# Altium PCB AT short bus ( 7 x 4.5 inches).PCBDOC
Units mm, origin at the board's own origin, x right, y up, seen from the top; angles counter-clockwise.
Board outline 100 x 65 mm, 2 copper layers (TopLayer, BottomLayer); 8 components, 31 nets, 75 pads, 17 vias.
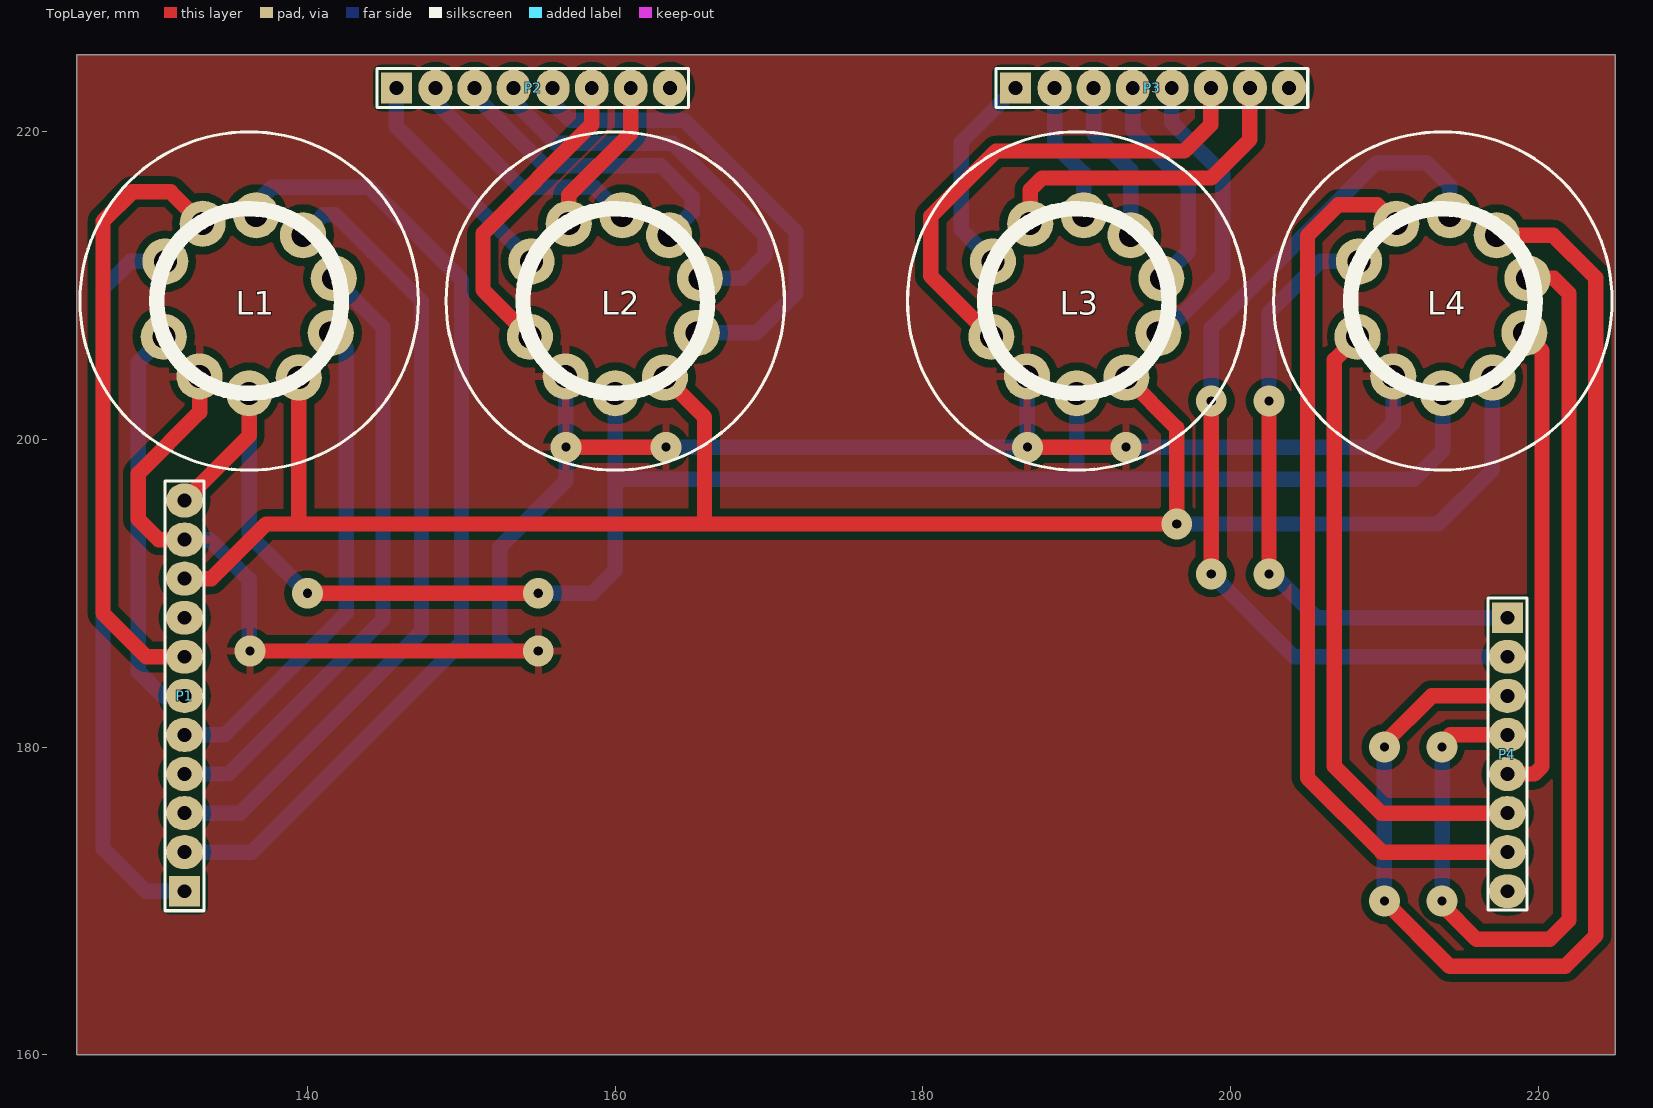
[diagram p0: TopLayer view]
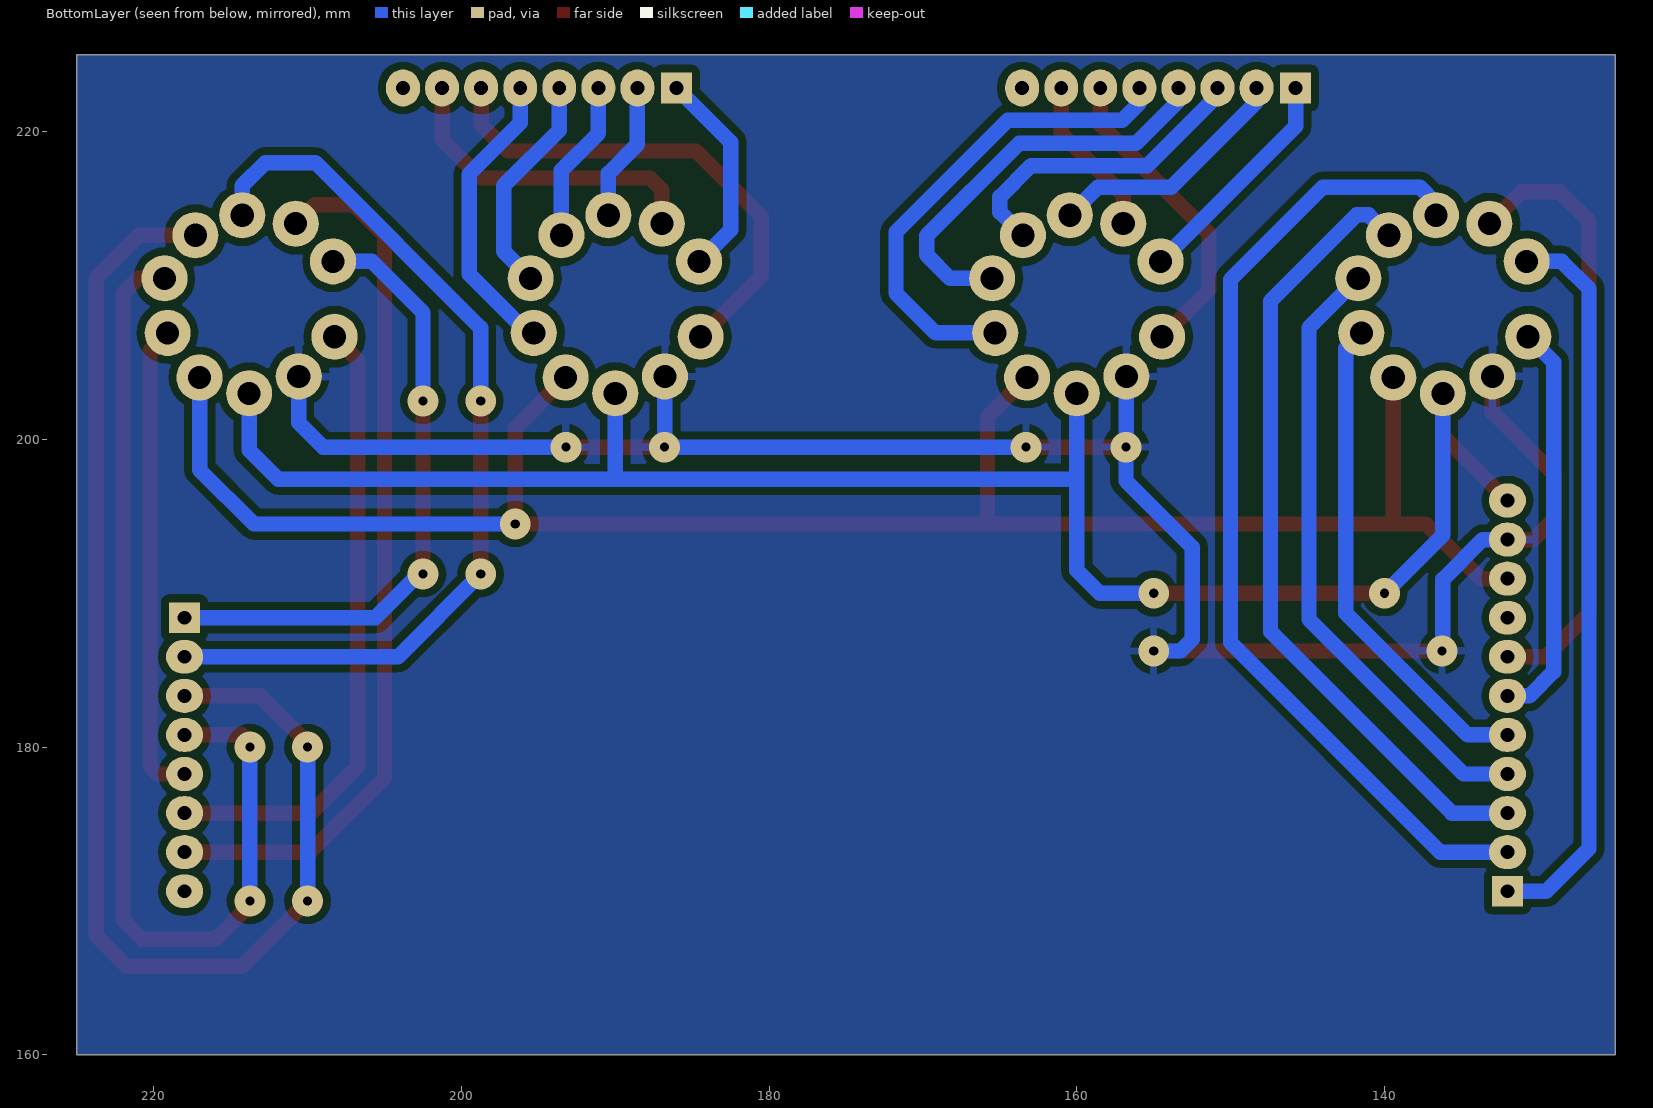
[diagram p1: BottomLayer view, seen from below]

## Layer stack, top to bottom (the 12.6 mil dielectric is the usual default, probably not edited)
TopSolder: solder mask 0.0102, Solder Resist, Dk 3.5
TopLayer: signal copper 0.0356
Dielectric1: core 0.32, FR-4, Dk 4.8
BottomLayer: signal copper 0.0356
BottomSolder: solder mask 0.0102, Solder Resist, Dk 3.5

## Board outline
125,225 225,225 225,160 125,160

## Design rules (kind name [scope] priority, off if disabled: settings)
Clearance [All] p1: gap=0.5 ignorepadtopadclearanceinfootprint=FALSE except(0: Arc-Hole Track-Hole SMDPad-Hole THPad-Hole Via-Hole Fill-Hole Poly-Hole Region-Hole Text-Hole)
FabricationTestPointUsage TestPointUsage [All] p1: valid=0 allowmultiple=FALSE
FabricationTestpoint Testpoint [All] p1: side=3 testpointundercomponent=TRUE minsize=1.016 maxsize=2.54 preferedsize=1.524 minholesize=0.508 maxholesize=1.016 preferedholesize=0.813 testpointgrid=0.025 allowsidetop=TRUE allowsidebottom=TRUE usegrid=TRUE gridtolerance=0
PasteMaskExpansion PasteMaskExpansion_1 [InComponent('P1')] p1: expansion=-3.81
PasteMaskExpansion [All] p2: expansion=0
PlaneClearance [All] p1: clearance=0.254
PolygonConnect [All] p1: connectstyle=Relief reliefconductorwidth=0.5 reliefentries=4 polygonreliefangle="90 Angle" airgapwidth=0.5
RoutingVias [All] p1: holewidth=0.711 width=1.27 viastyle="Through Hole" minholewidth=0.711 minwidth=1.27 maxholewidth=0.711 maxwidth=1.27
SilkToSolderMaskClearance SilkscreenOverComponentPads [IsPad] p1: minsilkscreentomaskgap=0.254 clearancetoexposedcopper=TRUE
SolderMaskExpansion [All] p1: expansion=0.051
Width [All] p1: maxlimit=2 minlimit=0.254 preferedwidth=1
25 further rules are at their usual default settings.

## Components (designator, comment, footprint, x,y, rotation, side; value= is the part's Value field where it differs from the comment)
L1 "IV-12" IV-12 136.2,209 r0 top
L2 "IV-12" IV-12 160,209 r0 top
L3 "IV-12" IV-12 190,209 r0 top
L4 "IV-12" IV-12 213.8,209 r0 top
P1 "Header 11" HDR1X11 132,170.63 r90 top
P2 "Header 8" HDR1X8 145.77,222.85 r0 top
P3 "Header 8" HDR1X8 186.02,222.85 r0 top
P4 "Header 8" HDR1X8 218,188.41 r270 top

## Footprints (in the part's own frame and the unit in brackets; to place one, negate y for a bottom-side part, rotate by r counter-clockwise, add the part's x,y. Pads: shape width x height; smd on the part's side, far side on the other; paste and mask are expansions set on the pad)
HDR1X8 [mm] "Connector; Header; 11 Position"
  rect 2x2 hole 0.9: 1(0,0)
  oval 2.2x2.4 hole 0.9: 2(2.54,0) 3(5.08,0) 4(7.62,0) 5(10.16,0) 6(12.7,0) 7(15.24,0) 8(17.78,0)
  silkscreen extent -1.27,-1.27 19,1.27
HDR1X11 [mm] "Connector; Header; 11 Position"
  rect 2x2 hole 0.9: 1(0,0)
  oval 2.2x2.4 hole 0.9: 2(2.54,0) 3(5.08,0) 4(7.62,0) 5(10.16,0) 6(12.7,0) 7(15.24,0) 8(17.78,0) 9(20.32,0) 10(22.86,0) 11(25.4,0)
  silkscreen extent -1.27,-1.27 26.67,1.27
IV-12 [mm]
  round 3 hole 1.5: 1(-5.55,-2.325) 2(-3.225,-4.9) 3(0,-6) 4(3.225,-4.975) 5(5.3,-2.075) 6(5.5,1.475) 7(3.5,4.275) 8(0.45,5.575) 9(-3.025,5.025) 10(-5.45,2.575)
  silkscreen extent -11,-11 11,11

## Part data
L1 L2 L3 L4: library part Lamp1_IV-12
P1: "Header, 11-Pin"
P2 P3 P4: "Header, 8-Pin"

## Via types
v1: diameter 2, hole 0.6, TopLayer to BottomLayer, 17 vias

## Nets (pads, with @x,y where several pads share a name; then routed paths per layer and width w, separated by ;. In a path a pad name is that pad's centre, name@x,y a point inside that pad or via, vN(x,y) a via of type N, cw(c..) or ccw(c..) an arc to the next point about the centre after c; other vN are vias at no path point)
Glow1: L1.3 L2.3 L3.3 L4.3 P1.11 | length 119.4
  TopLayer w1: P1.11 136.2,200.23 L1.3 ; v1(140,190) v1(155,190)
  BottomLayer w1: L1.3 136.2,193.8 v1(140,190) ; v1(155,190) 158.5,190 160,191.5 160,197.4 ; L2.3 160,197.4 ; L3.3 190,197.6 189.8,197.4 ; L4.3 213.8,199.3 211.9,197.4 189.8,197.4 ; 160,197.4 189.8,197.4
Glow2: L1.2 L2.2 L3.2 L4.2 P1.10 | length 126.7
  TopLayer w1: P1.10 130.31,193.49 129,194.8 129,197.8 132.975,201.775 L1.2 ; v1(136.25,186.25) v1(155,186.25) ; v1@156.7,199.5 v1(156.8,199.5) v1(163.3,199.5) ; v1(186.8,199.5) v1@193,199.5
  BottomLayer w1: P1.10 133.61,193.49 136.2,190.9 v1@136.2,186.5 ; v1(155,186.25) 153.25,186.25 152.5,187 152.5,193 156.8,197.3 v1(156.8,199.5) 156.775,199.525 L2.2 ; v1@163.1,199.5 v1(163.3,199.5) v1@186.775,199.5 ; v1@186.775,199.775 L3.2 ; v1@193,199.5 v1(193.2,199.5) 209,199.5 210.575,201.075 L4.2
Grid: L1.4 L2.4 L3.4 L4.4 P1.9 | length 124.5
  TopLayer w1: P1.9 133.75,190.95 137.3,194.5 v1(196.5,194.5) 196.5,200.75 L3.4 ; 139.425,194.75 L1.4 ; L2.4 165.8,201.45 165.8,194.75
  BottomLayer w1: v1(196.5,194.5) 213.5,194.5 217.025,198.025 L4.4
L1_a: L1.10 P1.1 | length 47.6
  BottomLayer w1: L1.10 128.475,211.575 126.7,209.8 126.7,173.4 129.47,170.63 P1.1
L1_b: L1.8 P1.2 | length 64.3
  BottomLayer w1: P1.2 136.37,173.17 150,186.8 150,210.4 144,216.4 137.7,216.4 136.65,215.35 L1.8
L1_c: L1.7 P1.3 | length 52.4
  BottomLayer w1: P1.3 135.61,175.71 147.4,187.5 147.4,209 141.8,214.6 141.025,214.6 L1.7
L1_d: L1.6 P1.4 | length 40.6
  BottomLayer w1: P1.4 134.85,178.25 144.9,188.3 144.9,207.275 L1.6
L1_e: L1.5 P1.5 | length 32.4
  BottomLayer w1: P1.5 134.59,180.79 142.5,188.7 142.5,205.925 L1.5
L1_f: L1.1 P1.6 | length 26.1
  BottomLayer w1: L1.1 129,205.025 129,184.9 130.57,183.33 P1.6
L1_g: L1.9 P1.7 | length 40.1
  TopLayer w1: P1.7 129.53,185.87 126.7,188.7 126.7,214.2 128.6,216.1 131.1,216.1 L1.9
L2_a: L2.10 P2.1 | length 14.9
  BottomLayer w1: P2.1 145.77,220.355 L2.10
L2_b: L2.8 P2.2 | length 16.1
  BottomLayer w1: P2.2 148.31,221.94 153.85,216.4 158.625,216.4 L2.8
L2_c: L2.7 P2.3 | length 19.9
  BottomLayer w1: P2.3@150.9,222.3 155.4,217.8 162.975,217.8 165,215.775 165,214.775 L2.7
L2_d: L2.6 P2.4 | length 27
  BottomLayer w1: P2.4 153.39,222.01 156.15,219.25 163.75,219.25 169.75,213.25 169.75,212 168.225,210.475 L2.6
L2_e: L2.5 P2.5 | length 31.8
  BottomLayer w1: P2.5 155.93,221.87 157.05,220.75 164.5,220.75 171.75,213.5 171.75,209.5 169.175,206.925 L2.5
L2_f: L2.1 P2.6 | length 20.4
  TopLayer w1: L2.1 151.4,209.725 151.4,213.4 158.47,220.47 P2.6
L2_g: L2.9 P2.7 | length 10.5
  TopLayer w1: L2.9 156.975,215.875 161.01,219.91 P2.7
L4_a: L3.10 P3.1 | length 13.6
  BottomLayer w1: L3.10 182.5,213.625 182.5,219.33 P3.1
L4_b: L3.8 P3.2 | length 9.1
  BottomLayer w1: P3.2 188.56,219.19 190.45,217.3 L3.8
L4_c: L3.7 P3.3 | length 10.6
  BottomLayer w1: P3.3 191.1,219.9 193.5,217.5 L3.7
L4_d: L3.6 P3.4 | length 14.6
  BottomLayer w1: P3.4 193.64,220.11 197.25,216.5 197.25,212.225 L3.6
L4_e: L3.5 P3.5 | length 19.3
  BottomLayer w1: L3.5 195.675,206.925 199.5,210.75 199.5,217.25 196.18,220.57 P3.5
L4_f: L3.1 P3.6 | length 32.5
  TopLayer w1: L3.1 180.5,210.625 180.5,214.5 184.75,218.75 197,218.75 198.72,220.47 P3.6
L4_g: L3.9 P3.7 | length 21.2
  TopLayer w1: L3.9 186.975,216.225 187.75,217 198.75,217 201.26,219.51 P3.7
L5_a: L4.10 P4.1 | length 39.9
  TopLayer w1: v1(202.5,191.25) v1(202.5,202.5)
  BottomLayer w1: v1@202.5,203.25 202.5,208.25 205.825,211.575 L4.10 ; v1@202.75,191.25 205.59,188.41 P4.1
L5_b: L4.8 P4.2 | length 60
  TopLayer w1: v1(198.75,191.25) v1(198.75,202.5)
  BottomLayer w1: v1(198.75,191.25) 204.13,185.87 P4.2 ; v1(198.75,202.5) 198.75,207.25 209.5,218 212.75,218 214.25,216.5 L4.8
L5_c: L4.7 P4.3 | length 86.1
  TopLayer w1: v1@209.875,180.125 213.08,183.33 P4.3 ; v1(210,170) 214.25,165.75 221.75,165.75 223.75,167.75 223.75,210.5 220.975,213.275 L4.7
  BottomLayer w1: v1(210,170) v1(210,180)
L5_d: L4.6 P4.4 | length 68.4
  TopLayer w1: v1@213.5,180 214.29,180.79 P4.4 ; v1@213.75,169.75 216,167.5 220.75,167.5 222,168.75 222,209.5 221.025,210.475 L4.6
  BottomLayer w1: v1(213.75,170) v1(213.75,180)
L5_e: L4.5 P4.5 | length 31.1
  TopLayer w1: P4.5 219.75,178.25 220.25,178.75 220.25,205.775 L4.5
L5_f: L4.1 P4.6 | length 41.1
  TopLayer w1: L4.1 206.75,205.175 206.75,178.75 209.79,175.71 P4.6
L5_g: L4.9 P4.7 | length 57.4
  TopLayer w1: L4.9 209.55,215.25 207,215.25 205,213.25 205,178 209.83,173.17 P4.7
pads on no net: P1.8 P2.8 P3.8 P4.8

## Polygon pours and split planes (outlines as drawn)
Glow2 on TopLayer "Top Layer-No Net" (solid, remove dead copper, pour order 4): 125,225 225,225 225,160 125,160
Glow2 on BottomLayer "Top Layer-No Net" (solid, remove dead copper, pour order 6): 125,225 225,225 225,160 125,160

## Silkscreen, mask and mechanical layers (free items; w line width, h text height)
Mechanical1:
  lines w0.2: 190,225 225,225 ; 225,225 125,225 125,160 225,160 225,225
